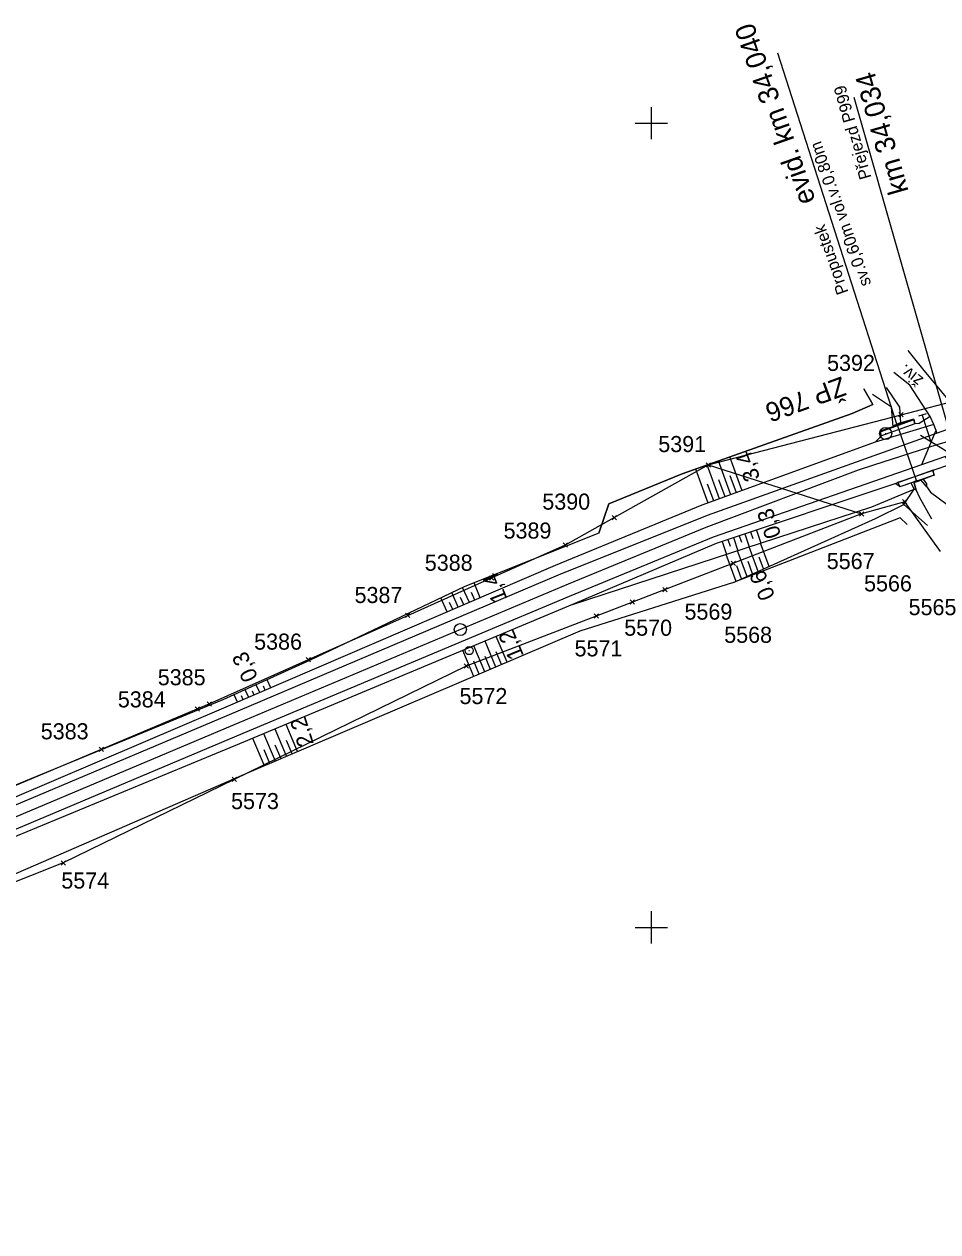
# Model space of a CAD drawing. Extents: x -805730 to -804640, y -1150889 to -1150366.
# Drawn here: x -804978 to -804864.4, y -1150637.9 to -1150487.7 of the extents above; entities that cross this region are included whole.
import ezdxf

# ---------------------------------------------------------------- set-up
doc = ezdxf.new("R2010")
doc.units = 0
for name, color, linetype in [('0381KM032-037P - Vrstva 1', 7, 'Continuous'), ('0381KM032-037P - Vrstva 17', 7, 'Continuous'), ('0381KM032-037P - Vrstva 19', 7, 'Continuous'), ('0381KM032-037P - Vrstva 4', 7, 'Continuous'), ('0381KM032-037P - Vrstva 48', 7, 'Continuous'), ('0381KM032-037P - Vrstva 49', 7, 'Continuous'), ('0381KM032-037P - Vrstva 51', 7, 'Continuous'), ('0381KM032-037P - Vrstva 55', 7, 'Continuous'), ('0381KM032-037P - Vrstva 7', 7, 'Continuous'), ('krizky_1000 - Vrstva 1', 7, 'Continuous'), ('szdc - hran DP', 7, 'Continuous'), ('szdc - szdc_cislo', 7, 'Continuous'), ('szdc - szdc_krizek', 7, 'Continuous'), ('vyt_sit - ohrožené', 7, 'Continuous')]:
    doc.layers.add(name, color=color, linetype=linetype)

msp = doc.modelspace()

# ---------------------------------------------------------------- linework, layer by layer
at = {"layer": '0381KM032-037P - Vrstva 1'}
for points in [[(-804836.89, -1150533.13), (-804845.84, -1150535.01), (-804855.06, -1150537.3), (-804860.78, -1150538.93), (-804864.46, -1150539.98), (-804872.35, -1150542.54)], [(-804872.35, -1150542.54), (-804874.25, -1150543.16), (-804893.23, -1150550.28), (-804910.33, -1150557.31)], [(-804910.33, -1150557.31), (-804952.12, -1150574.92), (-804994.42, -1150592.71), (-805038.63, -1150611.27), (-805057.71, -1150619.3), (-805074.24, -1150626.27)]]:
    msp.add_lwpolyline(points, dxfattribs=at)
at = {"layer": '0381KM032-037P - Vrstva 17'}
for p, q in [((-804873.58, -1150533.02), (-804873.58, -1150533.02)), ((-804867.35, -1150536.9), (-804871.44, -1150538.39))]:
    msp.add_line(p, q, dxfattribs=at)
for points in [[(-804734.71, -1150510.96), (-804735.96, -1150513.84), (-804741.77, -1150514.83), (-804760.36, -1150517.2), (-804795.4, -1150521.06), (-804816.51, -1150523.78), (-804835.4, -1150526.88), (-804850, -1150530.66), (-804863.08, -1150534.36), (-804866.23, -1150530.55), (-804868.05, -1150528.28)], [(-804873.58, -1150533.02), (-804872.42, -1150534.97), (-804875, -1150536.1), (-804896.18, -1150543.61), (-804905.28, -1150547.35), (-804906.51, -1150551)], [(-804868.16, -1150549.89), (-804869.02, -1150549.09), (-804889.78, -1150557.12), (-804908.89, -1150563.18), (-804949.8, -1150580.61), (-804991.45, -1150598.69), (-805036.34, -1150617.58)], [(-804906.51, -1150551), (-804923.2, -1150557.6), (-804942.52, -1150566.83), (-804953.3, -1150571.71), (-804995.99, -1150589.23), (-805040.03, -1150605.68), (-805044.15, -1150607.13)]]:
    msp.add_lwpolyline(points, dxfattribs=at)
at = {"layer": '0381KM032-037P - Vrstva 19'}
for p, q in [((-804869.43, -1150537.57), (-804884.27, -1150491.28)), ((-804867.32, -1150536.83), (-804871.54, -1150538.31)), ((-804866.95, -1150544.56), (-804869.42, -1150537.44)), ((-804867.2, -1150537.4), (-804867.36, -1150536.8)), ((-804871.36, -1150538.86), (-804871.49, -1150538.28)), ((-804864.83, -1150543.77), (-804869.08, -1150545.22)), ((-804869.27, -1150544.65), (-804869.59, -1150544.8)), ((-804869.59, -1150544.8), (-804869.04, -1150545.2)), ((-804867.71, -1150544.71), (-804867.31, -1150545.53))]:
    msp.add_line(p, q, dxfattribs=at)
for points in [[(-804871.36, -1150538.86), (-804871.54, -1150538.31), (-804867.32, -1150536.83), (-804867.2, -1150537.4), (-804871.36, -1150538.86)], [(-804871.54, -1150538.31), (-804871.54, -1150538.31), (-804871.49, -1150538.28), (-804869.89, -1150537.71)], [(-804869.89, -1150537.71), (-804869.42, -1150537.44), (-804868.94, -1150537.26)], [(-804867.32, -1150536.83), (-804867.32, -1150536.83), (-804867.36, -1150536.8), (-804868.94, -1150537.26)], [(-804865.03, -1150543.19), (-804864.83, -1150543.77), (-804869.08, -1150545.22), (-804869.27, -1150544.65), (-804865.03, -1150543.19)], [(-804866.16, -1150544.27), (-804864.91, -1150543.76), (-804864.83, -1150543.77), (-804864.83, -1150543.77)], [(-804865.03, -1150543.19), (-804864.94, -1150543.15), (-804864.91, -1150543.76)], [(-804869.08, -1150545.22), (-804869.08, -1150545.22), (-804869.04, -1150545.2), (-804867.71, -1150544.71), (-804867.33, -1150544.58)], [(-804867.33, -1150544.58), (-804867.03, -1150545.63), (-804867.31, -1150545.53)]]:
    msp.add_lwpolyline(points, dxfattribs=at)
msp.add_lwpolyline([(-804866.45, -1150544.36), (-804866.16, -1150544.27), (-804865.77, -1150544.86), (-804865.78, -1150545.2)], close=True, dxfattribs=at)
for centre, major_axis, ratio in [((-804869.43, -1150537.43), (-0.407, -0.192), 0.02514), ((-804866.89, -1150544.48), (0.45, 0.118), 0.13222)]:
    msp.add_ellipse(centre, major_axis=major_axis, ratio=ratio, dxfattribs=at)
at = {"layer": '0381KM032-037P - Vrstva 4'}
for p, q in [((-804874.8, -1150496.75), (-804862.62, -1150539.46)), ((-804865.82, -1150536.14), (-804866.77, -1150536.45)), ((-804866.3, -1150536.29), (-804865.21, -1150539.62)), ((-804862.58, -1150541.24), (-804866.52, -1150538.84)), ((-804864.62, -1150538.22), (-804866.38, -1150542.48))]:
    msp.add_line(p, q, dxfattribs=at)
for points in [[(-804864.42, -1150538.53), (-804864.84, -1150537.45), (-804872.17, -1150539.66)], [(-804864.42, -1150538.53), (-804893.06, -1150548.77), (-804911.6, -1150556.2), (-804952.82, -1150573.68), (-804994.86, -1150591.44), (-805039.39, -1150610.13), (-805056.71, -1150617.44), (-805097.6, -1150634.39)], [(-804872.17, -1150539.66), (-804893.72, -1150547.52), (-804911.96, -1150555), (-804952.93, -1150572.63), (-804995.29, -1150590.69), (-805039.86, -1150609.18), (-805057.83, -1150616.69), (-805068.36, -1150621.07), (-805097.92, -1150633.57)], [(-804862.73, -1150542.41), (-804863.39, -1150541.46), (-804892.29, -1150551.48), (-804910.22, -1150558.86), (-804951.61, -1150576.23), (-804993.7, -1150593.96), (-805038.63, -1150612.92), (-805049.62, -1150617.53), (-805055.59, -1150619.94), (-805066.74, -1150624.75), (-805096.44, -1150637.01)], [(-804864.94, -1150543.15), (-804869.59, -1150544.8), (-804891.93, -1150552.26), (-804909.8, -1150559.87), (-804951.24, -1150577.2), (-804993.38, -1150594.6), (-805038.39, -1150613.8), (-805059.54, -1150622.79), (-805066.49, -1150625.57), (-805096.25, -1150637.87)], [(-804864.94, -1150543.15), (-804862.73, -1150542.41), (-804862.73, -1150542.41)]]:
    msp.add_lwpolyline(points, dxfattribs=at)
at = {"layer": '0381KM032-037P - Vrstva 48'}
for p, q in [((-804890.12, -1150546.21), (-804891.64, -1150542)), ((-804888.71, -1150545.7), (-804890.22, -1150541.5)), ((-804892.94, -1150547.24), (-804894.46, -1150543.01)), ((-804891.53, -1150546.73), (-804893.05, -1150542.5)), ((-804889.42, -1150545.95), (-804890.17, -1150543.85)), ((-804892.24, -1150546.98), (-804893, -1150544.87)), ((-804890.83, -1150546.47), (-804891.59, -1150544.36)), ((-804889.06, -1150551.3), (-804888.79, -1150552.11)), ((-804888.35, -1150551.06), (-804887.81, -1150552.69)), ((-804887.64, -1150550.83), (-804887.36, -1150551.65)), ((-804886.92, -1150550.59), (-804886.38, -1150552.23)), ((-804891.19, -1150552.02), (-804890.66, -1150553.62)), ((-804890.48, -1150551.78), (-804890.21, -1150552.58)), ((-804889.77, -1150551.54), (-804889.23, -1150553.16)), ((-804886.72, -1150555.74), (-804887.83, -1150552.7)), ((-804885.35, -1150555.12), (-804886.41, -1150552.24)), ((-804889.46, -1150556.98), (-804890.69, -1150553.63)), ((-804888.09, -1150556.36), (-804889.26, -1150553.17)), ((-804886.03, -1150555.43), (-804886.58, -1150553.95)), ((-804888.78, -1150556.67), (-804889.37, -1150555.03)), ((-804887.4, -1150556.05), (-804887.97, -1150554.49)), ((-804921.28, -1150559.01), (-804922.05, -1150557.14)), ((-804924.01, -1150560.18), (-804924.82, -1150558.38)), ((-804922.63, -1150559.59), (-804923.47, -1150557.73)), ((-804921.97, -1150559.3), (-804922.36, -1150558.36)), ((-804925.38, -1150560.77), (-804926.18, -1150559.02)), ((-804924.69, -1150560.48), (-804925.1, -1150559.59)), ((-804923.32, -1150559.88), (-804923.73, -1150558.97)), ((-804919.33, -1150567.63), (-804920.68, -1150564.42)), ((-804917.95, -1150567.04), (-804919.3, -1150563.84)), ((-804922.08, -1150568.8), (-804923.45, -1150565.58)), ((-804920.71, -1150568.22), (-804922.06, -1150565)), ((-804920.02, -1150567.92), (-804920.69, -1150566.31)), ((-804918.64, -1150567.33), (-804919.31, -1150565.73)), ((-804921.4, -1150568.51), (-804922.08, -1150566.9)), ((-804947.33, -1150570.22), (-804947.78, -1150569.21)), ((-804950.09, -1150571.4), (-804950.51, -1150570.45)), ((-804949.4, -1150571.11), (-804949.61, -1150570.62)), ((-804948.71, -1150570.81), (-804949.14, -1150569.83)), ((-804948.02, -1150570.52), (-804948.24, -1150570.02)), ((-804951.47, -1150572), (-804951.88, -1150571.07)), ((-804950.78, -1150571.7), (-804950.99, -1150571.23)), ((-804945.38, -1150578.73), (-804946.81, -1150575.35)), ((-804944, -1150578.14), (-804945.43, -1150574.77)), ((-804948.14, -1150579.91), (-804949.58, -1150576.51)), ((-804946.76, -1150579.32), (-804948.19, -1150575.93)), ((-804944.69, -1150578.44), (-804945.4, -1150576.75)), ((-804947.45, -1150579.61), (-804948.17, -1150577.92)), ((-804946.07, -1150579.03), (-804946.79, -1150577.33))]:
    msp.add_line(p, q, dxfattribs=at)
at = {"layer": '0381KM032-037P - Vrstva 49'}
for p, q in [((-804867.85, -1150532.57), (-804869.83, -1150530.99)), ((-804872.42, -1150534.97), (-804873.58, -1150533.02)), ((-804865.31, -1150536.46), (-804867.85, -1150532.57)), ((-804867.03, -1150545.63), (-804867.33, -1150544.58)), ((-804865.78, -1150545.2), (-804866.45, -1150544.36)), ((-804868.59, -1150547.42), (-804865.62, -1150550.04))]:
    msp.add_line(p, q, dxfattribs=at)
for points in [[(-804868.94, -1150537.26), (-804869.09, -1150535.33), (-804870.73, -1150532.86)], [(-804869.89, -1150537.71), (-804870.12, -1150535.33), (-804872.5, -1150533.72)], [(-804906.51, -1150551), (-804905.28, -1150547.35), (-804896.18, -1150543.61), (-804875, -1150536.1), (-804872.42, -1150534.97)], [(-804871.36, -1150538.86), (-804871.49, -1150538.28), (-804869.89, -1150537.71)], [(-804865.31, -1150536.46), (-804866.66, -1150537.33), (-804867.2, -1150537.4), (-804871.36, -1150538.86)], [(-804868.94, -1150537.26), (-804867.36, -1150536.8), (-804867.2, -1150537.4)], [(-804871.36, -1150538.86), (-804872.17, -1150539.66), (-804893.72, -1150547.52), (-804911.96, -1150555), (-804952.93, -1150572.63), (-804995.29, -1150590.69), (-805039.86, -1150609.18), (-805057.83, -1150616.69), (-805068.36, -1150621.07), (-805097.92, -1150633.57)], [(-804869.27, -1150544.65), (-804865.03, -1150543.19), (-804864.94, -1150543.15), (-804862.73, -1150542.41)], [(-804869.27, -1150544.65), (-804869.59, -1150544.8), (-804891.93, -1150552.26), (-804909.8, -1150559.87)], [(-804865.78, -1150545.2), (-804865.26, -1150545.89), (-804862.25, -1150548.13)], [(-804909.8, -1150559.87), (-804872.57, -1150547.72), (-804867.31, -1150545.53)], [(-804889.78, -1150557.12), (-804872.12, -1150549.16), (-804868.59, -1150547.42), (-804867.31, -1150545.53)], [(-804867.03, -1150545.63), (-804866.68, -1150546.48), (-804865.14, -1150549.2)], [(-804906.51, -1150551), (-804923.2, -1150557.6), (-804942.52, -1150566.83), (-804953.3, -1150571.71), (-804995.99, -1150589.23), (-805040.03, -1150605.68), (-805044.15, -1150607.13)], [(-804889.78, -1150557.12), (-804908.89, -1150563.18), (-804949.8, -1150580.61), (-804991.45, -1150598.69), (-805036.34, -1150617.58)], [(-804909.8, -1150559.87), (-804951.24, -1150577.2), (-804993.38, -1150594.6), (-805038.39, -1150613.8), (-805050.01, -1150619.25), (-805055.21, -1150621.51), (-805059.54, -1150622.79), (-805066.49, -1150625.57), (-805096.25, -1150637.87)]]:
    msp.add_lwpolyline(points, dxfattribs=at)
msp.add_ellipse((-804866.89, -1150544.48), major_axis=(0.45, 0.118), ratio=0.13222, start_param=2.866376, end_param=6.348957, dxfattribs=at)
at = {"layer": '0381KM032-037P - Vrstva 51'}
msp.add_line((-804867.85, -1150532.57), (-804869.83, -1150530.99), dxfattribs=at)
for points in [[(-804864.84, -1150537.45), (-804865.31, -1150536.46), (-804867.85, -1150532.57)], [(-804861.98, -1150536.58), (-804861.64, -1150537.54), (-804864.42, -1150538.53), (-804864.84, -1150537.45)]]:
    msp.add_lwpolyline(points, dxfattribs=at)
at = {"layer": '0381KM032-037P - Vrstva 55'}
msp.add_line((-804892.91, -1150542.49), (-804873.83, -1150548.59), dxfattribs=at)
at = {"layer": '0381KM032-037P - Vrstva 7'}
msp.add_line((-804922.71, -1150565.59), (-804922.61, -1150565.59), dxfattribs=at)
for centre, radius in [((-804923.76, -1150562.97), 0.75), ((-804922.66, -1150565.59), 0.5)]:
    msp.add_circle(centre, radius, dxfattribs=at)
at = {"layer": 'krizky_1000 - Vrstva 1'}
for points in [[(-804900, -1150498), (-804900, -1150502)], [(-804902, -1150500), (-804898, -1150500)], [(-804900, -1150598), (-804900, -1150602)], [(-804902, -1150600), (-804898, -1150600)]]:
    msp.add_lwpolyline(points, dxfattribs=at)
at = {"layer": 'szdc - hran DP'}
for p, q in [((-804868.93, -1150536.25), (-804855.75, -1150532.82)), ((-804892.91, -1150542.49), (-804868.93, -1150536.25)), ((-804904.62, -1150549.05), (-804892.91, -1150542.49)), ((-804868.47, -1150547.08), (-804873.83, -1150548.59)), ((-804864.02, -1150553.26), (-804868.47, -1150547.08)), ((-804910.68, -1150552.45), (-804904.62, -1150549.05)), ((-804873.83, -1150548.59), (-804889.79, -1150554.73)), ((-804919.88, -1150556.55), (-804910.68, -1150552.45)), ((-804889.79, -1150554.73), (-804898.28, -1150557.99)), ((-804930.31, -1150561.21), (-804919.88, -1150556.55)), ((-804898.28, -1150557.99), (-804902.34, -1150559.55)), ((-804902.34, -1150559.55), (-804906.85, -1150561.29)), ((-804942.65, -1150566.71), (-804930.31, -1150561.21)), ((-804906.85, -1150561.29), (-804923.02, -1150567.51)), ((-804954.99, -1150572.21), (-804942.65, -1150566.71)), ((-804923.02, -1150567.51), (-804951.89, -1150581.61)), ((-804956.48, -1150572.84), (-804954.99, -1150572.21)), ((-804968.41, -1150577.86), (-804956.48, -1150572.84)), ((-804981, -1150583.16), (-804968.41, -1150577.86)), ((-804951.89, -1150581.61), (-804973.16, -1150591.99)), ((-804973.16, -1150591.99), (-805001.53, -1150603.08))]:
    msp.add_line(p, q, dxfattribs=at)
at = {"layer": 'szdc - szdc_krizek'}
for p, q in [((-804868.67, -1150536.52), (-804869.2, -1150535.99)), ((-804869.2, -1150536.52), (-804868.67, -1150535.99)), ((-804892.65, -1150542.76), (-804893.18, -1150542.23)), ((-804893.18, -1150542.76), (-804892.65, -1150542.23)), ((-804868.21, -1150547.34), (-804868.74, -1150546.81)), ((-804868.74, -1150547.34), (-804868.21, -1150546.81)), ((-804873.57, -1150548.85), (-804874.1, -1150548.32)), ((-804874.1, -1150548.85), (-804873.57, -1150548.32)), ((-804904.35, -1150549.31), (-804904.89, -1150548.78)), ((-804904.89, -1150549.31), (-804904.35, -1150548.78)), ((-804910.42, -1150552.72), (-804910.95, -1150552.19)), ((-804910.95, -1150552.72), (-804910.42, -1150552.19)), ((-804889.53, -1150555), (-804890.06, -1150554.47)), ((-804890.06, -1150555), (-804889.53, -1150554.47)), ((-804919.61, -1150556.81), (-804920.15, -1150556.28)), ((-804920.15, -1150556.81), (-804919.61, -1150556.28)), ((-804898.02, -1150558.26), (-804898.55, -1150557.73)), ((-804898.55, -1150558.26), (-804898.02, -1150557.73)), ((-804902.08, -1150559.81), (-804902.61, -1150559.28)), ((-804902.61, -1150559.81), (-804902.08, -1150559.28)), ((-804930.05, -1150561.48), (-804930.58, -1150560.95)), ((-804930.58, -1150561.48), (-804930.05, -1150560.95)), ((-804906.58, -1150561.55), (-804907.12, -1150561.03)), ((-804907.12, -1150561.55), (-804906.58, -1150561.03)), ((-804942.39, -1150566.98), (-804942.92, -1150566.45)), ((-804942.92, -1150566.98), (-804942.39, -1150566.45)), ((-804922.76, -1150567.78), (-804923.29, -1150567.25)), ((-804923.29, -1150567.78), (-804922.76, -1150567.25)), ((-804954.72, -1150572.48), (-804955.26, -1150571.95)), ((-804955.26, -1150572.48), (-804954.72, -1150571.95)), ((-804956.21, -1150573.1), (-804956.75, -1150572.57)), ((-804956.75, -1150573.1), (-804956.21, -1150572.57)), ((-804968.15, -1150578.12), (-804968.68, -1150577.59)), ((-804968.68, -1150578.12), (-804968.15, -1150577.59)), ((-804951.62, -1150581.88), (-804952.16, -1150581.34)), ((-804952.16, -1150581.88), (-804951.62, -1150581.34)), ((-804972.9, -1150592.26), (-804973.43, -1150591.73)), ((-804973.43, -1150592.26), (-804972.9, -1150591.73))]:
    msp.add_line(p, q, dxfattribs=at)
at = {"layer": 'vyt_sit - ohrožené'}
msp.add_line((-804870.89, -1150538.58), (-804870.79, -1150538.58), dxfattribs=at)
msp.add_circle((-804870.84, -1150538.58), 0.756, dxfattribs=at)

# ---------------------------------------------------------------- texts
at = {"layer": '0381KM032-037P - Vrstva 19'}
for s, height, rotation, p in [('evid. km 34,040', 2.5, 109.3587, (-804879.52, -1150509.62)), ('sv.0,60m vol.v.0,80m', 1.5, 109.4315, (-804872.62, -1150520)), ('Propustek', 1.5, 109.4315, (-804875.45, -1150521))]:
    msp.add_text(s, height=height, rotation=rotation, dxfattribs=at).set_placement(p)
at = {"layer": '0381KM032-037P - Vrstva 4'}
for s, height, rotation, p in [('km 34,034', 2.5, 106.0257, (-804867.97, -1150508.45)), ('Přejezd P999', 1.5, 105.8715, (-804872.6, -1150506.75))]:
    msp.add_text(s, height=height, rotation=rotation, dxfattribs=at).set_placement(p)
at = {"layer": '0381KM032-037P - Vrstva 48'}
for s, rotation, p in [('3,4', 110.0448, (-804886.43, -1150544.12)), ('0,3', 108.4626, (-804883.82, -1150551.25)), ('0,6', 113.0694, (-804884.56, -1150558.81)), ('1,4', 111.5655, (-804917.87, -1150559.18)), ('1,2', 112.6972, (-804915.82, -1150566.2)), ('0,3', 114.3346, (-804948.89, -1150568.92)), ('2,2', 107.6972, (-804941.96, -1150577.16))]:
    msp.add_text(s, height=2, rotation=rotation, dxfattribs=at).set_placement(p)
at = {"layer": '0381KM032-037P - Vrstva 51'}
msp.add_text('živ.', height=1.5, rotation=141.4462, dxfattribs=at).set_placement((-804866.05, -1150531.74))
at = {"layer": 'szdc - szdc_cislo'}
for s, p in [('5392', (-804878.13, -1150530.81)), ('5391', (-804899.13, -1150540.9)), ('5390', (-804913.56, -1150548.06)), ('5389', (-804918.38, -1150551.66)), ('5388', (-804928.18, -1150555.66)), ('5567', (-804878.17, -1150555.45)), ('5566', (-804873.53, -1150558.22)), ('5387', (-804936.92, -1150559.67)), ('5569', (-804895.87, -1150561.74)), ('5565', (-804867.99, -1150561.18)), ('5570', (-804903.37, -1150563.74)), ('5568', (-804890.93, -1150564.62)), ('5386', (-804949.41, -1150565.47)), ('5571', (-804909.55, -1150566.31)), ('5385', (-804961.4, -1150569.9)), ('5384', (-804966.37, -1150572.65)), ('5572', (-804923.86, -1150572.24)), ('5383', (-804975.96, -1150576.62)), ('5573', (-804952.28, -1150585.3)), ('5574', (-804973.4, -1150595.18))]:
    msp.add_text(s, height=2, dxfattribs=at).set_placement(p)
at = {"layer": 'vyt_sit - ohrožené'}
msp.add_text('ŽP 766', height=2.4, rotation=200, dxfattribs=at).set_placement((-804876.31, -1150531.46))

doc.saveas('drawing.dxf')
